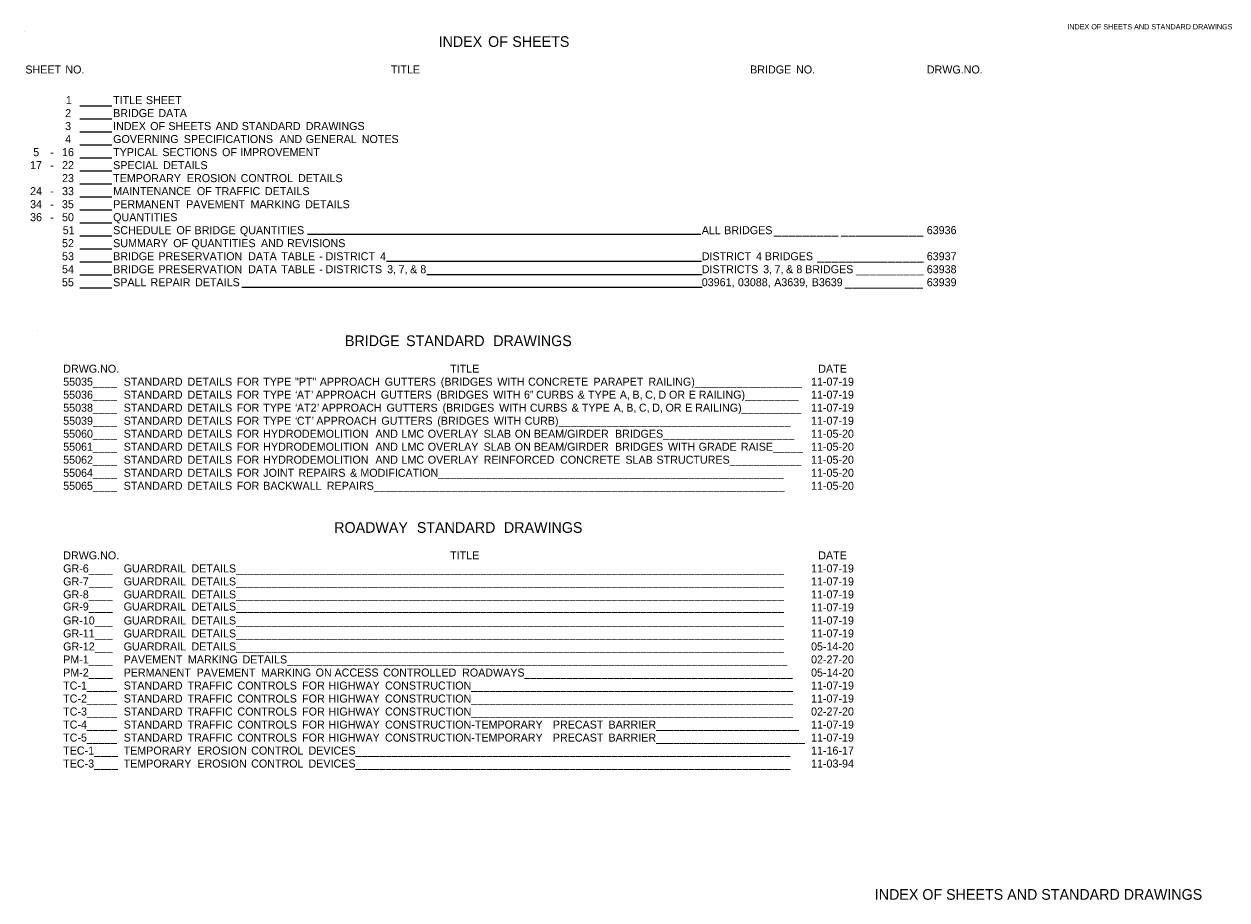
# Model space of a CAD drawing. Extents: x 1930579 to 1935331, y 596452 to 598347.
import ezdxf

# ---------------------------------------------------------------- set-up
doc = ezdxf.new("R2010")
doc.units = 0
for name, color, linetype in [('Default', 7, 'Continuous'), ('R_Border', 7, 'Continuous'), ('R_Border Prem', 7, 'Continuous')]:
    doc.layers.add(name, color=color, linetype=linetype)

msp = doc.modelspace()

# ---------------------------------------------------------------- linework, layer by layer
at = {"layer": 'Default'}
for p, q in [((1934041.5, 598254.9), (1934077.3, 598254.9)), ((1934041.5, 598240.3), (1934077.3, 598240.3)), ((1934041.5, 598225.7), (1934077.3, 598225.7)), ((1934041.5, 598211.1), (1934077.3, 598211.1)), ((1934041.5, 598196.4), (1934077.3, 598196.4)), ((1934041.5, 598181.8), (1934077.3, 598181.8)), ((1934041.5, 598167.2), (1934077.3, 598167.2)), ((1934041.5, 598152.6), (1934077.3, 598152.6)), ((1934041.5, 598137.9), (1934077.3, 598137.9)), ((1934041.5, 598123.3), (1934077.3, 598123.3)), ((1934041.5, 598108.7), (1934077.3, 598108.7)), ((1934739.5, 598110), (1934297.4, 598110)), ((1934041.5, 598094.1), (1934077.3, 598094.1)), ((1934041.5, 598079.4), (1934077.3, 598079.4)), ((1934386.2, 598080.3), (1934740.2, 598080.3)), ((1934041.5, 598064.8), (1934077.3, 598064.8)), ((1934431.5, 598065.2), (1934741.2, 598065.2)), ((1934041.5, 598050.2), (1934077.3, 598050.2)), ((1934741.2, 598050.6), (1934223.6, 598050.6))]:
    msp.add_line(p, q, dxfattribs=at)
at = {"layer": 'R_Border'}
for p, q in [((1933978.6, 598338.3), (1933978.6, 598338.3)), ((1933994.1, 598002), (1933994.1, 598002))]:
    msp.add_line(p, q, dxfattribs=at)

# ---------------------------------------------------------------- texts
at = {"layer": 'Default'}
for s, height, p in [('INDEX', 12, (1934444.7, 598321)), (' OF', 12, (1934495.9, 598321)), (' SHEETS', 12, (1934523.1, 598321)), ('SHEET', 9, (1933980.1, 598291.1)), (' NO.', 9, (1934021.7, 598291.1)), ('TITLE', 9, (1934391.1, 598291.1)), ('BRIDGE', 9, (1934795, 598291.1)), (' NO.', 9, (1934843.3, 598291.1)), ('DRWG.NO.', 9, (1934993.7, 598291.1)), ('1', 9, (1934025.6, 598256.7)), ('TITLE', 9, (1934078.8, 598256.7)), (' SHEET', 9, (1934112.3, 598256.7)), ('2', 9, (1934024.8, 598242.1)), ('BRIDGE', 9, (1934078.8, 598242.1)), (' DATA', 9, (1934126.3, 598242.1)), ('3', 9, (1934024.8, 598227.5)), ('INDEX', 9, (1934078.8, 598227.5)), (' OF', 9, (1934117.1, 598227.5)), (' SHEETS', 9, (1934137.5, 598227.5)), (' AND', 9, (1934190.7, 598227.5)), (' STANDARD', 9, (1934220, 598227.5)), (' DRAWINGS', 9, (1934292, 598227.5)), ('4', 9, (1934024.8, 598212.9)), ('GOVERNING', 9, (1934078.8, 598212.9)), (' SPECIFICATIONS', 9, (1934154.9, 598212.9)), (' AND', 9, (1934262.5, 598212.9)), (' GENERAL', 9, (1934291.9, 598212.9)), (' NOTES', 9, (1934355, 598212.9)), ('5', 9, (1933988.9, 598198.2)), ('-', 9, (1934008.1, 598198.2)), ('16', 9, (1934021.3, 598198.2)), ('TYPICAL', 9, (1934078.8, 598198.2)), (' SECTIONS', 9, (1934130.8, 598198.2)), (' OF', 9, (1934197.9, 598198.2)), (' IMPROVEMENT', 9, (1934218.3, 598198.2)), ('17', 9, (1933985.4, 598183.6)), ('-', 9, (1934008.1, 598183.6)), ('22', 9, (1934021.3, 598183.6)), ('SPECIAL', 9, (1934078.8, 598183.6)), (' DETAILS', 9, (1934131.5, 598183.6)), ('23', 9, (1934021.3, 598169)), ('TEMPORARY', 9, (1934078.8, 598169)), (' EROSION', 9, (1934158.4, 598169)), (' CONTROL', 9, (1934218.8, 598169)), (' DETAILS', 9, (1934283.3, 598169)), ('24', 9, (1933985.4, 598154.4)), ('-', 9, (1934008.1, 598154.4)), ('33', 9, (1934021.3, 598154.4)), ('MAINTENANCE', 9, (1934078.8, 598154.4)), (' OF', 9, (1934169.6, 598154.4)), (' TRAFFIC', 9, (1934190, 598154.4)), (' DETAILS', 9, (1934246.1, 598154.4)), ('34', 9, (1933985.4, 598139.7)), ('-', 9, (1934008.1, 598139.7)), ('35', 9, (1934021.2, 598139.7)), ('PERMANENT', 9, (1934078.8, 598139.7)), (' PAVEMENT', 9, (1934157.5, 598139.7)), (' MARKING', 9, (1934229.9, 598139.7)), (' DETAILS', 9, (1934291.3, 598139.7)), ('36', 9, (1933985.4, 598125.1)), ('-', 9, (1934008.1, 598125.1)), ('50', 9, (1934021.3, 598125.1)), ('QUANTITIES', 9, (1934078.8, 598125.1)), ('51', 9, (1934022.1, 598110.5)), ('SCHEDULE', 9, (1934078.8, 598110.5)), (' OF', 9, (1934146.6, 598110.5)), (' BRIDGE', 9, (1934167, 598110.5)), (' QUANTITIES', 9, (1934218, 598110.5)), ('ALL', 9, (1934740.6, 598110.5)), (' BRIDGES', 9, (1934762.5, 598110.5)), ('63936', 9, (1934993.6, 598110.5)), ('52', 9, (1934021.3, 598095.9)), ('SUMMARY', 9, (1934078.8, 598095.9)), (' OF', 9, (1934143, 598095.9)), (' QUANTITIES', 9, (1934163.4, 598095.9)), (' AND', 9, (1934241.6, 598095.9)), (' REVISIONS', 9, (1934271, 598095.9)), ('53', 9, (1934021.3, 598081.2)), ('BRIDGE', 9, (1934078.8, 598081.2)), (' PRESERVATION', 9, (1934126.3, 598081.2)), (' DATA', 9, (1934227.3, 598081.2)), (' TABLE', 9, (1934264.4, 598081.2)), (' DISTRICT', 9, (1934314.3, 598081.2)), (' 4', 9, (1934375.6, 598081.2)), ('DISTRICT', 9, (1934740.6, 598081.2)), (' 4', 9, (1934798.3, 598081.2)), (' BRIDGES', 9, (1934808.2, 598081.2)), ('63937', 9, (1934993.6, 598081.2)), ('54', 9, (1934021.3, 598066.6)), ('BRIDGE', 9, (1934078.8, 598066.6)), (' PRESERVATION', 9, (1934126.3, 598066.6)), (' DATA', 9, (1934227.3, 598066.6)), (' TABLE', 9, (1934264.4, 598066.6)), (' -', 9, (1934307, 598081.2)), (' DISTRICTS', 9, (1934314.3, 598066.6)), (' 3,', 9, (1934383.5, 598066.6)), (' 7,', 9, (1934396.4, 598066.6)), (' &', 9, (1934409.3, 598066.6)), (' 8', 9, (1934420.8, 598066.6)), ('DISTRICTS', 9, (1934740.6, 598066.6)), (' 3,', 9, (1934806.3, 598066.6)), (' 7,', 9, (1934819.1, 598066.6)), (' &', 9, (1934832, 598066.6)), (' 8', 9, (1934843.6, 598066.6)), (' BRIDGES', 9, (1934853.5, 598066.6)), ('63938', 9, (1934993.6, 598066.6)), ('55', 9, (1934021.2, 598052)), ('SPALL', 9, (1934078.8, 598052)), (' REPAIR', 9, (1934117.5, 598052)), (' DETAILS', 9, (1934167.6, 598052)), (' -', 9, (1934307, 598066.6)), ('03961,', 9, (1934740.6, 598052)), (' 03088,', 9, (1934777.9, 598052)), (' A3639,', 9, (1934818.7, 598052)), (' B3639', 9, (1934860.9, 598052)), ('63939', 9, (1934993.6, 598052)), ('BRIDGE', 12, (1934339.4, 597984.7)), (' STANDARD', 12, (1934403.7, 597984.7)), (' DRAWINGS', 12, (1934501.7, 597984.7)), ('DRWG.NO.', 9, (1934022.7, 597954.8)), ('TITLE', 9, (1934457.7, 597954.8)), ('DATE', 9, (1934871.6, 597954.8)), ('55035____', 9, (1934022.6, 597940.2)), ('STANDARD', 9, (1934090.6, 597940.2)), (' DETAILS', 9, (1934159.1, 597940.2)), (' FOR', 9, (1934214.3, 597940.2)), (' TYPE', 9, (1934244.2, 597940.2)), (' "PT"', 9, (1934279.9, 597940.2)), (' APPROACH', 9, (1934307.8, 597940.2)), (' GUTTERS', 9, (1934380.8, 597940.2)), (' (BRIDGES', 9, (1934443.8, 597940.2)), (' WITH', 9, (1934507.4, 597940.2)), (' CONCRETE', 9, (1934542, 597940.2)), (' PARAPET', 9, (1934615.4, 597940.2)), (' RAILING)__________________', 9, (1934677.3, 597940.2)), ('11-07-19', 9, (1934863.5, 597940.2)), ('55036____', 9, (1934022.6, 597925.6)), ('STANDARD', 9, (1934090.6, 597925.6)), (' DETAILS', 9, (1934159.1, 597925.6)), (' FOR', 9, (1934214.3, 597925.6)), (' TYPE', 9, (1934244.2, 597925.6)), ('‘', 9, (1934283.4, 597925.6)), ('AT', 9, (1934285.4, 597925.6)), ('’', 9, (1934301.3, 597925.6)), (' APPROACH', 9, (1934303.2, 597925.6)), (' GUTTERS', 9, (1934376.3, 597925.6)), (' (BRIDGES', 9, (1934439.2, 597925.6)), (' WITH', 9, (1934502.8, 597925.6)), (' 6', 9, (1934537.4, 597925.6)), ('”', 9, (1934547.3, 597925.6)), (' CURBS', 9, (1934551, 597925.6)), (' &', 9, (1934597.8, 597925.6)), (' TYPE', 9, (1934609.4, 597925.6)), (' A,', 9, (1934645.1, 597925.6)), (' B,', 9, (1934659.3, 597925.6)), (' C,', 9, (1934673.6, 597925.6)), (' D', 9, (1934688.5, 597925.6)), (' OR', 9, (1934700.4, 597925.6)), (' E', 9, (1934722.6, 597925.6)), (' RAILING)_________', 9, (1934733.8, 597925.6)), ('11-07-19', 9, (1934863.5, 597925.6)), ('55038____', 9, (1934022.6, 597911)), ('STANDARD', 9, (1934090.6, 597911)), (' DETAILS', 9, (1934159.1, 597911)), (' FOR', 9, (1934214.3, 597911)), (' TYPE', 9, (1934244.2, 597911)), ('‘', 9, (1934283.4, 597911)), ('AT2', 9, (1934285.4, 597911)), ('’', 9, (1934307.8, 597911)), (' APPROACH', 9, (1934309.8, 597911)), (' GUTTERS', 9, (1934382.8, 597911)), (' (BRIDGES', 9, (1934445.8, 597911)), (' WITH', 9, (1934509.4, 597911)), (' CURBS', 9, (1934544, 597911)), (' &', 9, (1934590.9, 597911)), (' TYPE', 9, (1934602.4, 597911)), (' A,', 9, (1934638.1, 597911)), (' B,', 9, (1934652.4, 597911)), (' C,', 9, (1934666.6, 597911)), (' D,', 9, (1934681.6, 597911)), (' OR', 9, (1934696.5, 597911)), (' E', 9, (1934718.7, 597911)), (' RAILING)__________', 9, (1934729.9, 597911)), ('11-07-19', 9, (1934863.5, 597911)), ('55039____', 9, (1934022.6, 597896.3)), ('STANDARD', 9, (1934090.6, 597896.3)), (' DETAILS', 9, (1934159.1, 597896.3)), (' FOR', 9, (1934214.3, 597896.3)), (' TYPE', 9, (1934244.2, 597896.3)), ('‘', 9, (1934283.4, 597896.3)), ('CT', 9, (1934285.4, 597896.3)), ('’', 9, (1934301.9, 597896.3)), (' APPROACH', 9, (1934303.9, 597896.3)), (' GUTTERS', 9, (1934377, 597896.3)), (' (BRIDGES', 9, (1934439.9, 597896.3)), (' WITH', 9, (1934503.5, 597896.3)), (' CURB)_______________________________________', 9, (1934538.1, 597896.3)), ('11-07-19', 9, (1934863.5, 597896.3)), ('55060____', 9, (1934022.6, 597881.7)), ('STANDARD', 9, (1934090.6, 597881.7)), (' DETAILS', 9, (1934159.1, 597881.7)), (' FOR', 9, (1934214.3, 597881.7)), (' HYDRODEMOLITION', 9, (1934244.2, 597881.7)), (' AND', 9, (1934370.3, 597881.7)), (' LMC', 9, (1934399.7, 597881.7)), (' OVERLAY', 9, (1934429.2, 597881.7)), (' SLAB', 9, (1934492, 597881.7)), (' ON', 9, (1934527, 597881.7)), (' BEAM/GIRDER', 9, (1934548.4, 597881.7)), (' BRIDGES______________________', 9, (1934639.7, 597881.7)), ('11-05-20', 9, (1934863.5, 597881.7)), ('55061____', 9, (1934022.6, 597867.1)), ('STANDARD', 9, (1934090.6, 597867.1)), (' DETAILS', 9, (1934159.1, 597867.1)), (' FOR', 9, (1934214.3, 597867.1)), (' HYDRODEMOLITION', 9, (1934244.2, 597867.1)), (' AND', 9, (1934370.3, 597867.1)), (' LMC', 9, (1934399.7, 597867.1)), (' OVERLAY', 9, (1934429.2, 597867.1)), (' SLAB', 9, (1934492, 597867.1)), (' ON', 9, (1934527, 597867.1)), (' BEAM/GIRDER', 9, (1934548.4, 597867.1)), (' BRIDGES', 9, (1934639.7, 597867.1)), (' WITH', 9, (1934699.2, 597867.1)), (' GRADE', 9, (1934733.8, 597867.1)), (' RAISE_____', 9, (1934781.3, 597867.1)), ('11-05-20', 9, (1934863.5, 597867.1)), ('55062____', 9, (1934022.6, 597852.5)), ('STANDARD', 9, (1934090.6, 597852.5)), (' DETAILS', 9, (1934159.1, 597852.5)), (' FOR', 9, (1934214.3, 597852.5)), (' HYDRODEMOLITION', 9, (1934244.2, 597852.5)), (' AND', 9, (1934370.3, 597852.5)), (' LMC', 9, (1934399.7, 597852.5)), (' OVERLAY', 9, (1934429.2, 597852.5)), (' REINFORCED', 9, (1934492, 597852.5)), (' CONCRETE', 9, (1934578, 597852.5)), (' SLAB', 9, (1934651.4, 597852.5)), (' STRUCTURES____________', 9, (1934686.4, 597852.5)), ('11-05-20', 9, (1934863.5, 597852.5)), ('55064____', 9, (1934022.6, 597837.8)), ('STANDARD', 9, (1934090.6, 597837.8)), (' DETAILS', 9, (1934159.1, 597837.8)), (' FOR', 9, (1934214.3, 597837.8)), (' JOINT', 9, (1934244.2, 597837.8)), (' REPAIRS', 9, (1934283.8, 597837.8)), (' &', 9, (1934341.8, 597837.8)), (' MODIFICATION__________________________________________________________', 9, (1934353.4, 597837.8)), ('11-05-20', 9, (1934863.5, 597837.8)), ('55065____', 9, (1934022.6, 597823.2)), ('STANDARD', 9, (1934090.6, 597823.2)), (' DETAILS', 9, (1934159.1, 597823.2)), (' FOR', 9, (1934214.3, 597823.2)), (' BACKWALL', 9, (1934244.2, 597823.2)), (' REPAIRS_____________________________________________________________________', 9, (1934315.7, 597823.2)), ('11-05-20', 9, (1934863.5, 597823.2)), ('ROADWAY', 12, (1934327.3, 597774.8)), (' STANDARD', 12, (1934415.8, 597774.8)), (' DRAWINGS', 12, (1934513.7, 597774.8)), ('DRWG.NO.', 9, (1934022.7, 597745)), ('TITLE', 9, (1934457.7, 597745)), ('DATE', 9, (1934871.6, 597745)), ('GR-6____', 9, (1934022.6, 597730.3)), ('GUARDRAIL', 9, (1934090.6, 597730.3)), (' DETAILS____________________________________________________________________________________________', 9, (1934163.5, 597730.3)), ('11-07-19', 9, (1934863.5, 597730.3)), ('GR-7____', 9, (1934022.6, 597715.7)), ('GUARDRAIL', 9, (1934090.6, 597715.7)), (' DETAILS____________________________________________________________________________________________', 9, (1934163.5, 597715.7)), ('11-07-19', 9, (1934863.5, 597715.7)), ('GR-8____', 9, (1934022.6, 597701.1)), ('GUARDRAIL', 9, (1934090.6, 597701.1)), (' DETAILS____________________________________________________________________________________________', 9, (1934163.5, 597701.1)), ('11-07-19', 9, (1934863.5, 597701.1)), ('GR-9____', 9, (1934022.6, 597687.5)), ('GUARDRAIL', 9, (1934090.6, 597687.5)), (' DETAILS____________________________________________________________________________________________', 9, (1934163.5, 597687.5)), ('11-07-19', 9, (1934863.5, 597686.5)), ('GR-10___', 9, (1934022.6, 597671.8)), ('GUARDRAIL', 9, (1934090.6, 597671.8)), (' DETAILS____________________________________________________________________________________________', 9, (1934163.5, 597671.8)), ('11-07-19', 9, (1934863.5, 597671.8)), ('GR-11___', 9, (1934022.6, 597657.2)), ('GUARDRAIL', 9, (1934090.6, 597657.2)), (' DETAILS____________________________________________________________________________________________', 9, (1934163.5, 597657.2)), ('11-07-19', 9, (1934863.5, 597657.2)), ('GR-12___', 9, (1934022.6, 597642.6)), ('GUARDRAIL', 9, (1934090.6, 597642.6)), (' DETAILS____________________________________________________________________________________________', 9, (1934163.5, 597642.6)), ('05-14-20', 9, (1934863.5, 597642.6)), ('PM-1____', 9, (1934022.6, 597628)), ('PAVEMENT', 9, (1934090.6, 597628)), (' MARKING', 9, (1934159.5, 597628)), (' DETAILS____________________________________________________________________________________', 9, (1934220.9, 597628)), ('02-27-20', 9, (1934863.5, 597628)), ('PM-2____', 9, (1934022.6, 597613.3)), ('PERMANENT', 9, (1934090.6, 597613.3)), (' PAVEMENT', 9, (1934169.3, 597613.3)), (' MARKING', 9, (1934241.7, 597613.3)), (' ON', 9, (1934303.1, 597613.3)), (' ACCESS', 9, (1934324.4, 597613.3)), (' CONTROLLED', 9, (1934379, 597613.3)), (' ROADWAYS_____________________________________________', 9, (1934467.8, 597613.3)), ('05-14-20', 9, (1934863.5, 597613.3)), ('TC-1_____', 9, (1934022.6, 597598.7)), ('STANDARD', 9, (1934090.6, 597598.7)), (' TRAFFIC', 9, (1934159.1, 597598.7)), (' CONTROLS', 9, (1934215.2, 597598.7)), (' FOR', 9, (1934287.9, 597598.7)), (' HIGHWAY', 9, (1934317.7, 597598.7)), (' CONSTRUCTION______________________________________________________', 9, (1934381.2, 597598.7)), ('11-07-19', 9, (1934863.5, 597598.7)), ('TC-2_____', 9, (1934022.6, 597584.1)), ('STANDARD', 9, (1934090.6, 597584.1)), (' TRAFFIC', 9, (1934159.1, 597584.1)), (' CONTROLS', 9, (1934215.2, 597584.1)), (' FOR', 9, (1934287.9, 597584.1)), (' HIGHWAY', 9, (1934317.7, 597584.1)), (' CONSTRUCTION______________________________________________________', 9, (1934381.2, 597584.1)), ('11-07-19', 9, (1934863.5, 597584.1)), ('TC-3_____', 9, (1934022.6, 597569.5)), ('STANDARD', 9, (1934090.6, 597569.5)), (' TRAFFIC', 9, (1934159.1, 597569.5)), (' CONTROLS', 9, (1934215.2, 597569.5)), (' FOR', 9, (1934287.9, 597569.5)), (' HIGHWAY', 9, (1934317.7, 597569.5)), (' CONSTRUCTION______________________________________________________', 9, (1934381.2, 597569.5)), ('02-27-20', 9, (1934863.5, 597569.5)), ('TC-4_____', 9, (1934022.6, 597554.8)), ('STANDARD', 9, (1934090.6, 597554.8)), (' TRAFFIC', 9, (1934159.1, 597554.8)), (' CONTROLS', 9, (1934215.2, 597554.8)), (' FOR', 9, (1934287.9, 597554.8)), (' HIGHWAY', 9, (1934317.7, 597554.8)), (' CONSTRUCTION-TEMPORARY', 9, (1934381.2, 597554.8)), (' PRECAST', 9, (1934569.8, 597554.8)), (' BARRIER________________________', 9, (1934632.4, 597554.8)), ('11-07-19', 9, (1934863.5, 597554.8)), ('TC-5_____', 9, (1934022.6, 597540.2)), ('STANDARD', 9, (1934090.6, 597540.2)), (' TRAFFIC', 9, (1934159.1, 597540.2)), (' CONTROLS', 9, (1934215.2, 597540.2)), (' FOR', 9, (1934287.9, 597540.2)), (' HIGHWAY', 9, (1934317.7, 597540.2)), (' CONSTRUCTION-TEMPORARY', 9, (1934381.2, 597540.2)), (' PRECAST', 9, (1934569.8, 597540.2)), (' BARRIER_________________________', 9, (1934632.4, 597540.2)), ('11-07-19', 9, (1934863.5, 597540.2)), ('TEC-1____', 9, (1934022.6, 597525.6)), ('TEMPORARY', 9, (1934090.6, 597525.6)), (' EROSION', 9, (1934170.1, 597525.6)), (' CONTROL', 9, (1934230.6, 597525.6)), (' DEVICES_________________________________________________________________________', 9, (1934295.1, 597525.6)), ('11-16-17', 9, (1934863.5, 597525.6)), ('TEC-3____', 9, (1934022.6, 597511)), ('TEMPORARY', 9, (1934090.6, 597511)), (' EROSION', 9, (1934170.1, 597511)), (' CONTROL', 9, (1934230.6, 597511)), (' DEVICES_________________________________________________________________________', 9, (1934295.1, 597511)), ('11-03-94', 9, (1934863.5, 597511))]:
    msp.add_text(s, height=height, rotation=360, dxfattribs=at).set_placement(p)
for height, p in [(10.8, (1934821.8, 598110.9)), (10.8, (1934897.5, 598110.9)), (10.8, (1934917.4, 598110.9)), (10.8, (1934870.5, 598081.6)), (10.8, (1934917.8, 598081.6)), (10.19, (1934914, 598067)), (10.19, (1934921.7, 598067)), (10.8, (1934901.6, 598052.4)), (10.8, (1934917, 598052.4))]:
    msp.add_text('_________', height=height, dxfattribs=at).set_placement(p)
at = {"layer": 'R_Border'}
msp.add_text('INDEX OF SHEETS AND STANDARD DRAWINGS', height=12, rotation=360, dxfattribs=at).set_placement((1934935.1, 597362.4))
at = {"layer": 'R_Border Prem'}
msp.add_text('INDEX OF SHEETS AND STANDARD DRAWINGS', height=5.862, rotation=360, dxfattribs=at).set_placement((1935151.6, 598340.7))

doc.saveas('drawing.dxf')
